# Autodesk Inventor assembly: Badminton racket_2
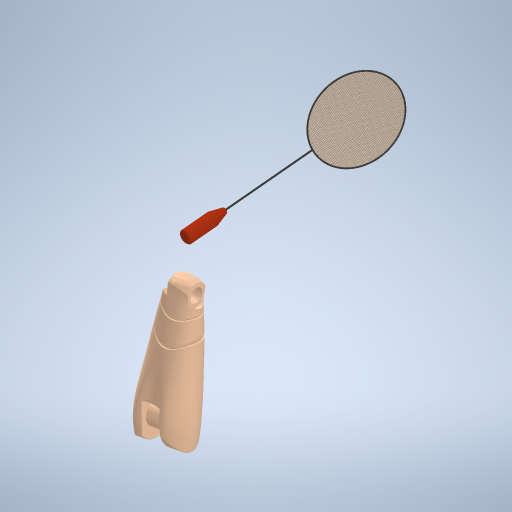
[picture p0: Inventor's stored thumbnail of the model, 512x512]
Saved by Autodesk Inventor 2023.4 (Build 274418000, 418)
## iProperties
Created: 2016-12
Part Number: Badminton racket_2
Material: Générique
Document SubType Name: Modeling
Designer: bruno
Density: 1 g/cm^3
Appearance: Par défaut
Author: bruno
Part Number: sachin racket
Created: 2017-03
Part Number: Badminton racket_Final
Document SubType Name: Assembly
Title: C:\Users\COEP\Desktop\Badminton racket_Final.stp
Author: COEP
Sending System: Autodesk Inventor 2017
Preprocessor: ST-DEVELOPER v16.5
Created: 2019-10
Part Number: Hand Full-badmington
Designer: yello
Author: yello
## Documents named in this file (8)
- **C:\Users\bruno\Documents\1-Cours-2025-26\1STI2D\ETLV\Diversité et inclusion\Hand Full-badmington.iam*LocalDocs*xAaaaakdaAaaaaaaaAaaaqvwvOd*Badminton racket_2.ipt
- **C:\Users\bruno\Documents\1-Cours-2025-26\1STI2D\ETLV\Diversité et inclusion\Hand Full-badmington.iam*LocalDocs*xAaaaa5baAaaaaaaaAaaaakuiZd*Badminton racket.ipt
- **C:\Users\bruno\Documents\1-Cours-2025-26\1STI2D\ETLV\Diversité et inclusion\Hand Full-badmington.iam*LocalDocs*xAaaaqidaAaaaaaaaAaaaqusx2a*Badminton racket.iam
- C:\Users\bruno\Documents\1-Cours-2025-26\1STI2D\ETLV\Diversité et inclusion\Hand Full-badmington.iam
- C:\Users\bruno\Documents\1-Cours-2025-26\1STI2D\ETLV\Diversité et inclusion\Prototype 2 (Realistic Hand)\Wrist Rotation.ipt
- C:\Users\bruno\Documents\1-Cours-2025-26\1STI2D\ETLV\Diversité et inclusion\Prototype 2 (Realistic Hand)\Arm to Wrist Connection.ipt
- C:\Users\bruno\Documents\1-Cours-2025-26\1STI2D\ETLV\Diversité et inclusion\Prototype 2 (Realistic Hand)\Arm.ipt
- C:\Users\bruno\Documents\1-Cours-2025-26\1STI2D\ETLV\Diversité et inclusion\Tools\Badminton racket.stp
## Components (4 placed, 4 different names)
1. Wrist Rotation:1 — Mate:1, Mate:2, Mate:4
2. Arm to Wrist Connection:1 — Mate:1, Mate:2, Mate:3
3. Arm:1 — Mate:3, Mate:4
4. Badminton racket:1 [sub-assembly]
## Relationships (4: Mate 4)
- Mate:1: Wrist Rotation:1 ↔ Arm to Wrist Connection:1
- Mate:2: Wrist Rotation:1 ↔ Arm to Wrist Connection:1
- Mate:3: Arm to Wrist Connection:1 ↔ Arm:1
- Mate:4: Wrist Rotation:1 ↔ Arm:1
